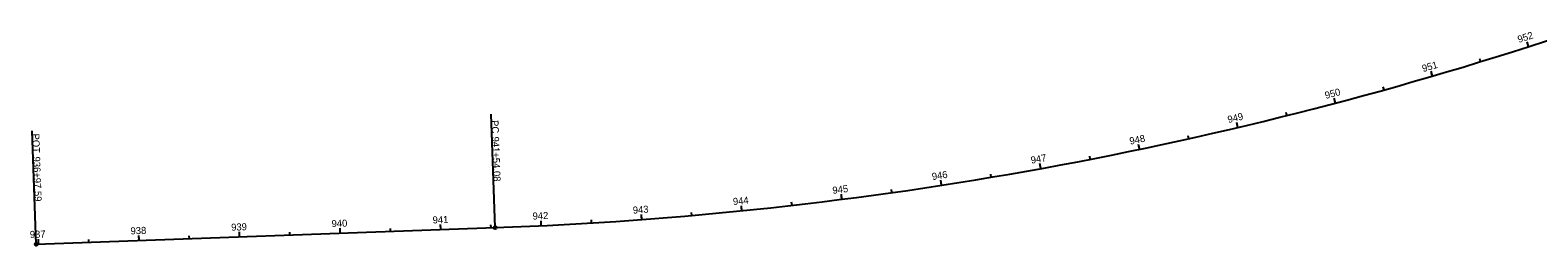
# Model space of a CAD drawing. Extents: x 2189048 to 2198002, y 659562 to 661773.
# Drawn here: x 2189048 to 2190546, y 659562 to 659775 of the extents above; entities that cross this region are included whole.
import ezdxf

# ---------------------------------------------------------------- set-up
doc = ezdxf.new("R2010")
doc.units = 0
for name, color, linetype in [('GE_X_Alignment', 7, 'Continuous'), ('GE_X_Alignment_1000_Stations', 7, 'Continuous'), ('GE_X_Alignment_100_Stations', 7, 'Continuous'), ('GE_X_Alignment_500_Stations', 7, 'Continuous')]:
    doc.layers.add(name, color=color, linetype=linetype)

msp = doc.modelspace()

# ---------------------------------------------------------------- linework, layer by layer
at = {"layer": 'GE_X_Alignment'}
msp.add_line((2189053.4, 659563.1), (2189509.6, 659579.5), dxfattribs=at)
msp.add_arc((2189372, 663396.7), 3819.7, 272.0655, 288.5329, dxfattribs=at)
at = {"layer": 'GE_X_Alignment_1000_Stations'}
for p, q in [((2190344.8, 659703), (2190343.5, 659707.8)), ((2189509.6, 659579.5), (2189505.6, 659691.9)), ((2189053.4, 659563.1), (2189049.4, 659675.5)), ((2189854.3, 659607.6), (2189853.9, 659610.6)), ((2189355.7, 659574), (2189355.5, 659578.9))]:
    msp.add_line(p, q, dxfattribs=at)
for centre in [(2189509.6, 659579.5), (2189053.4, 659563.1)]:
    msp.add_circle(centre, 1.5, dxfattribs=at)
at = {"layer": 'GE_X_Alignment_100_Stations'}
for p, q in [((2190536.7, 659758.9), (2190535.2, 659763.7)), ((2190489, 659744), (2190488.1, 659746.9)), ((2190441.1, 659729.7), (2190439.7, 659734.5)), ((2190393, 659716), (2190392.2, 659718.9)), ((2190344.8, 659703), (2190343.5, 659707.8)), ((2189509.6, 659579.5), (2189505.6, 659691.9)), ((2190247.7, 659678.8), (2190246.6, 659683.6)), ((2190296.3, 659690.6), (2190295.6, 659693.5)), ((2189053.4, 659563.1), (2189049.4, 659675.5)), ((2190199, 659667.6), (2190198.3, 659670.6)), ((2190101.1, 659647.3), (2190100.5, 659650.2)), ((2190150.1, 659657.1), (2190149.1, 659662)), ((2190051.9, 659638), (2190051.1, 659643)), ((2189953.3, 659621.5), (2189952.6, 659626.5)), ((2190002.7, 659629.5), (2190002.2, 659632.4)), ((2189804.7, 659601.6), (2189804.3, 659604.6)), ((2189854.3, 659607.6), (2189853.7, 659612.6)), ((2189903.9, 659614.2), (2189903.4, 659617.2)), ((2189655.3, 659587.5), (2189655, 659592.5)), ((2189705.2, 659591.6), (2189704.9, 659594.6)), ((2189754.9, 659596.3), (2189754.4, 659601.2)), ((2189255.7, 659570.3), (2189255.5, 659575.3)), ((2189305.7, 659572.1), (2189305.6, 659575.1)), ((2189355.7, 659574), (2189355.5, 659578.9)), ((2189405.6, 659575.8), (2189405.5, 659578.8)), ((2189455.6, 659577.6), (2189455.4, 659582.6)), ((2189505.6, 659579.4), (2189505.5, 659582.4)), ((2189555.5, 659581.4), (2189555.3, 659586.4)), ((2189605.4, 659584.2), (2189605.3, 659587.2)), ((2189055.9, 659563.1), (2189055.7, 659568.1)), ((2189105.8, 659564.9), (2189105.7, 659567.9)), ((2189155.8, 659566.7), (2189155.6, 659571.7)), ((2189205.8, 659568.5), (2189205.7, 659571.5))]:
    msp.add_line(p, q, dxfattribs=at)
for centre in [(2189509.6, 659579.5), (2189053.4, 659563.1)]:
    msp.add_circle(centre, 1.5, dxfattribs=at)
at = {"layer": 'GE_X_Alignment_500_Stations'}
for p, q in [((2190536.7, 659758.9), (2190535.8, 659761.8)), ((2190441.1, 659729.7), (2190440.3, 659732.6)), ((2190344.8, 659703), (2190343.5, 659707.8)), ((2189509.6, 659579.5), (2189505.6, 659691.9)), ((2190247.7, 659678.8), (2190247, 659681.7)), ((2189053.4, 659563.1), (2189049.4, 659675.5)), ((2190150.1, 659657.1), (2190149.5, 659660.1)), ((2190051.9, 659638), (2190051.4, 659641)), ((2189953.3, 659621.5), (2189952.9, 659624.5)), ((2189854.3, 659607.6), (2189853.7, 659612.6)), ((2189655.3, 659587.5), (2189655.1, 659590.5)), ((2189754.9, 659596.3), (2189754.6, 659599.3)), ((2189355.7, 659574), (2189355.5, 659578.9)), ((2189455.6, 659577.6), (2189455.5, 659580.6)), ((2189555.5, 659581.4), (2189555.4, 659584.4)), ((2189055.9, 659563.1), (2189055.7, 659566.1)), ((2189155.8, 659566.7), (2189155.7, 659569.7)), ((2189255.7, 659570.3), (2189255.6, 659573.3))]:
    msp.add_line(p, q, dxfattribs=at)
for centre in [(2189509.6, 659579.5), (2189053.4, 659563.1)]:
    msp.add_circle(centre, 1.5, dxfattribs=at)

# ---------------------------------------------------------------- texts
at = {"layer": 'GE_X_Alignment_1000_Stations'}
for s, rotation, p in [('950', 14.7544, (2190335.2, 659707)), ('PC', 272.0655, (2189505.9, 659685.9)), ('POT', 272.0655, (2189049.6, 659672.6)), ('941+54.08', 272.0655, (2189506.5, 659669.6)), ('936+97.59', 272.0655, (2189050.4, 659649.8)), ('940', 2.0655, (2189347.2, 659580))]:
    msp.add_text(s, height=7, rotation=rotation, dxfattribs=at).set_placement(p)
at = {"layer": 'GE_X_Alignment_100_Stations'}
for s, rotation, p in [('952', 17.7544, (2190527, 659762.5)), ('951', 16.2544, (2190431.9, 659733.6)), ('950', 14.7544, (2190335.2, 659707)), ('PC', 272.0655, (2189505.9, 659685.9)), ('949', 13.2544, (2190238.4, 659683.1)), ('POT', 272.0655, (2189049.6, 659672.6)), ('941+54.08', 272.0655, (2189506.5, 659669.6)), ('948', 11.7544, (2190140.8, 659661.7)), ('936+97.59', 272.0655, (2189050.4, 659649.8)), ('947', 10.2544, (2190042.6, 659642.8)), ('946', 8.7544, (2189944.2, 659626.6)), ('945', 7.2544, (2189845.3, 659612.9)), ('944', 5.7544, (2189746.3, 659601.8)), ('941', 2.0655, (2189447.6, 659583.6)), ('942', 2.7544, (2189547, 659587.4)), ('943', 4.2544, (2189646.7, 659593.3)), ('937', 2.0655, (2189047.3, 659569.2)), ('938', 2.0655, (2189147.4, 659572.8)), ('939', 2.0655, (2189247.4, 659576.4)), ('940', 2.0655, (2189347.2, 659580))]:
    msp.add_text(s, height=7, rotation=rotation, dxfattribs=at).set_placement(p)
at = {"layer": 'GE_X_Alignment_500_Stations'}
for s, rotation, p in [('950', 14.7544, (2190335.2, 659707)), ('PC', 272.0655, (2189505.9, 659685.9)), ('POT', 272.0655, (2189049.6, 659672.6)), ('941+54.08', 272.0655, (2189506.5, 659669.6)), ('936+97.59', 272.0655, (2189050.4, 659649.8)), ('945', 7.2544, (2189845.3, 659612.9)), ('940', 2.0655, (2189347.2, 659580))]:
    msp.add_text(s, height=7, rotation=rotation, dxfattribs=at).set_placement(p)

doc.saveas('drawing.dxf')
